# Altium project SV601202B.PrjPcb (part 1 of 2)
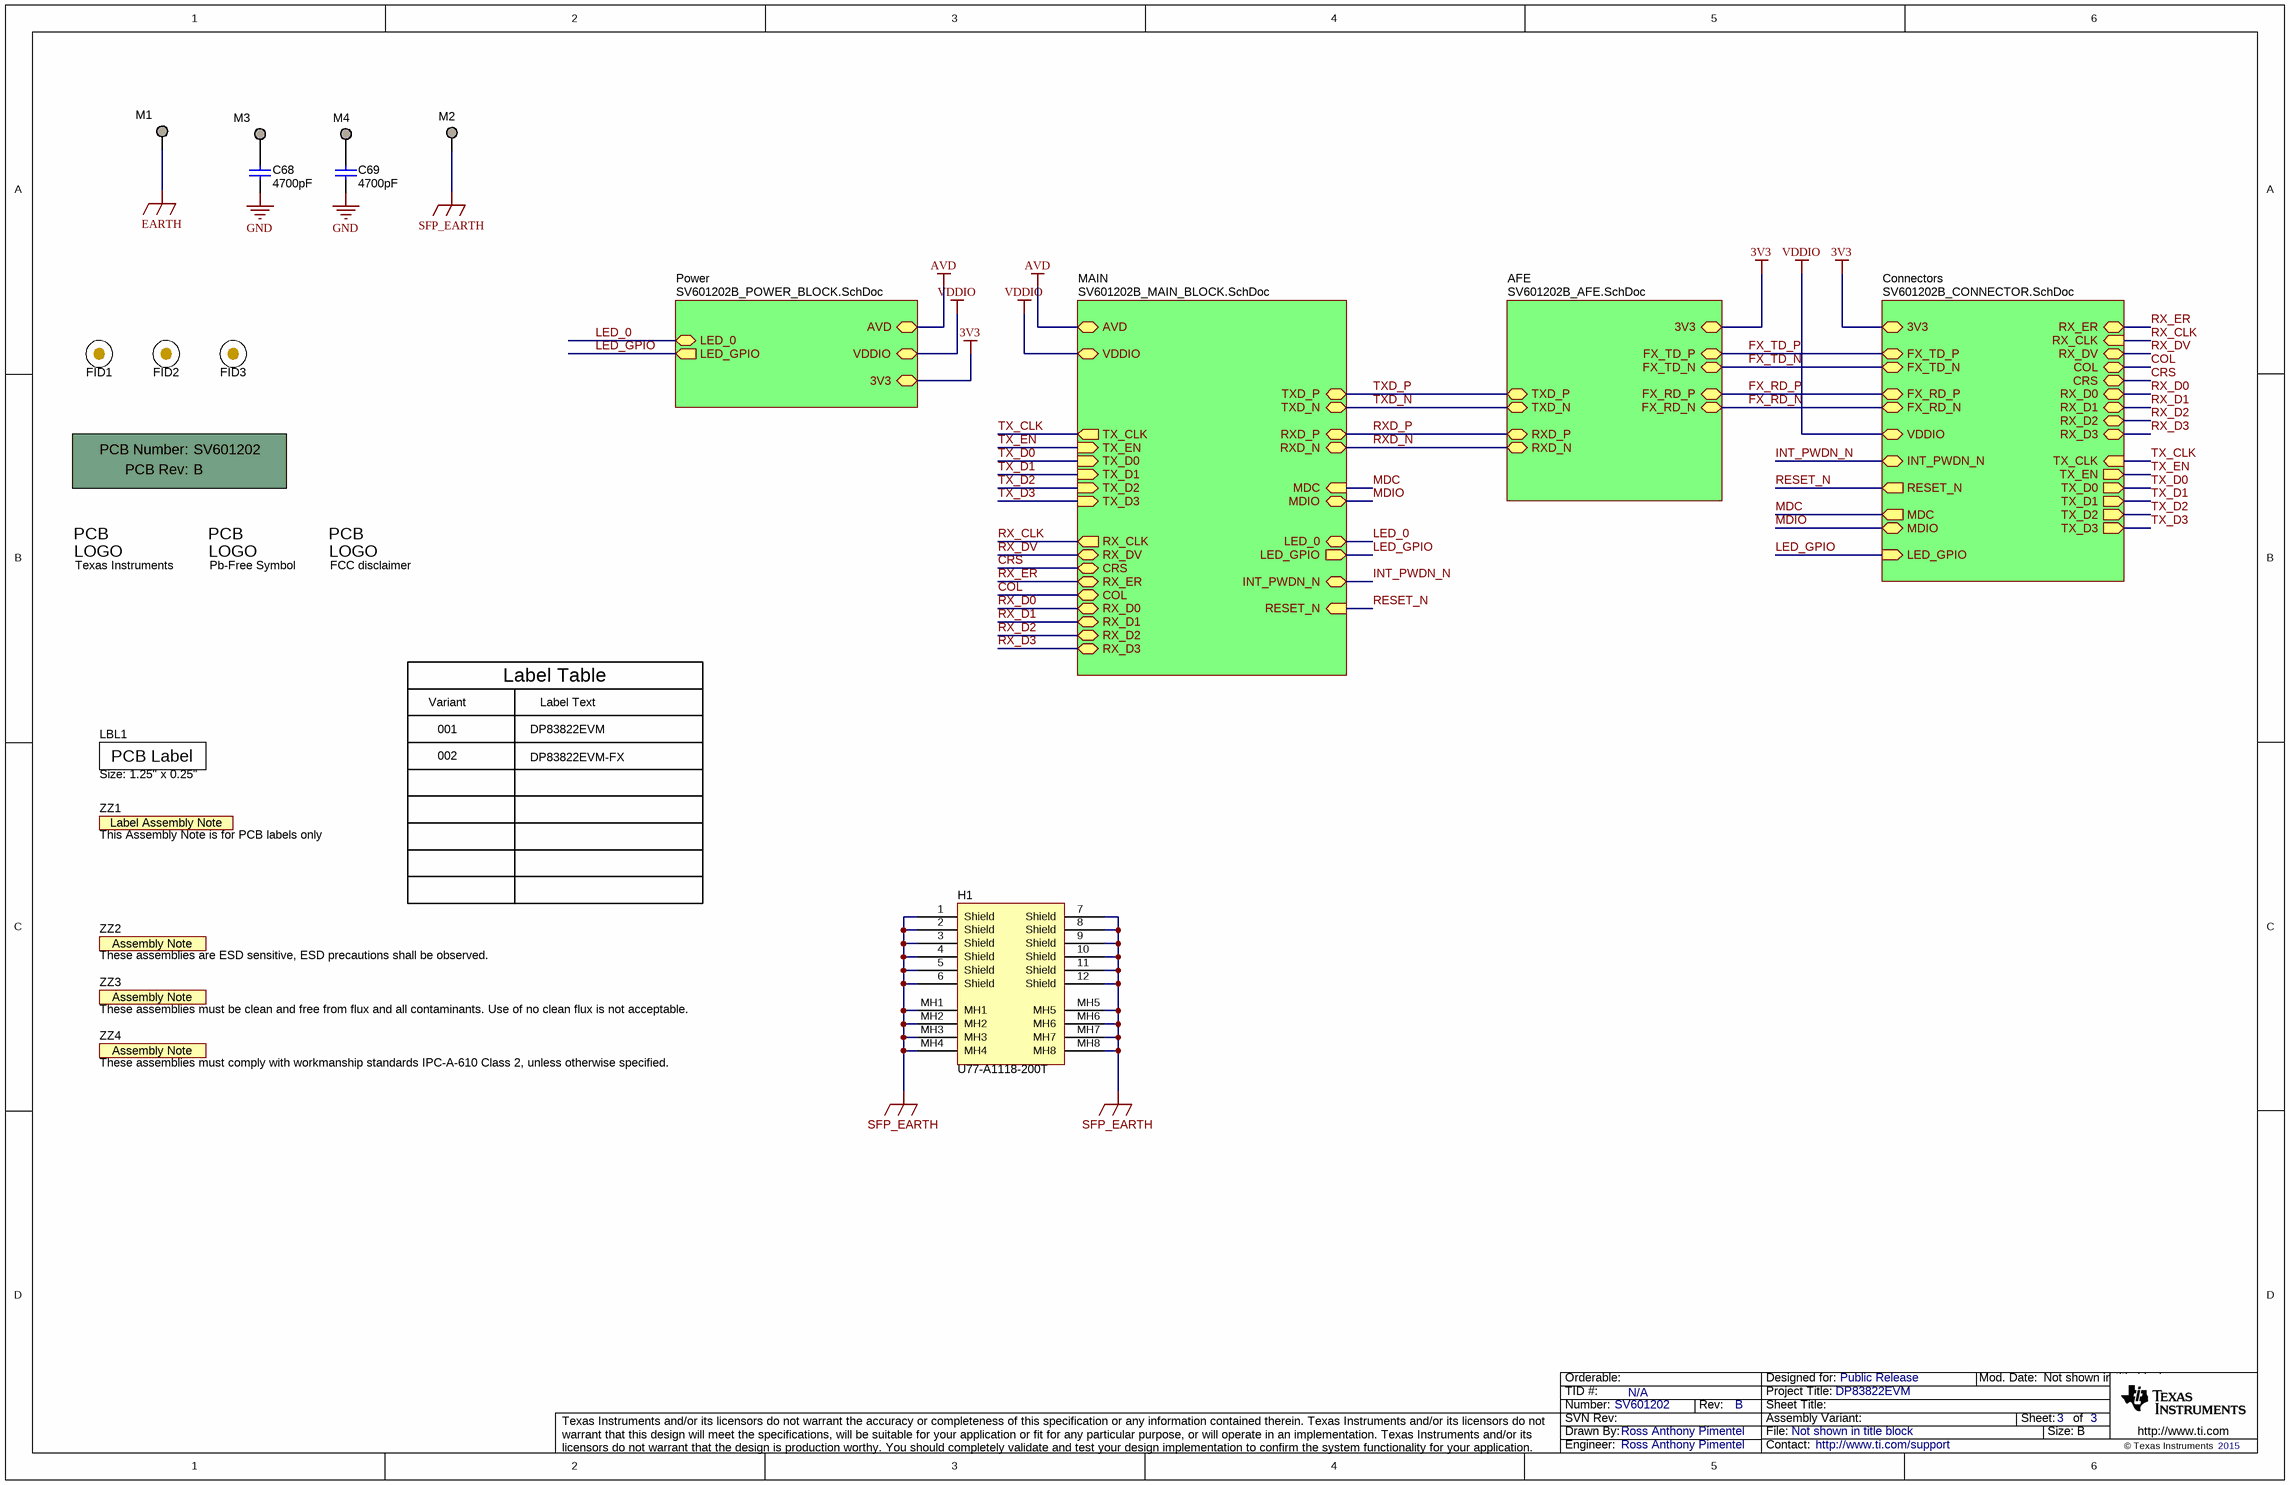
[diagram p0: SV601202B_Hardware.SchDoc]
CopyrightYear: 2015; PCB_Layout: Matthew Dillingham; PCB_Rev: B; PRJ_Customer: Public Release; PRJ_Engineer: Ross Anthony Pimentel; PRJ_Number: SV601202; PRJ_Title: DP83822EVM; SCH_Rev: B; TechSupport: http://www.ti.com/support; TID: N/A
5 sheets, 231 parts. Net scope: hierarchical (ports join the sheet entries above them; power ports are global).
Board file: SV601202B.PcbDoc
Sheets:
  SV601202B_Hardware.SchDoc
    AFE = SV601202B_AFE.SchDoc
    MAIN = SV601202B_MAIN_BLOCK.SchDoc
    Power = SV601202B_POWER_BLOCK.SchDoc
    Connectors = SV601202B_CONNECTOR.SchDoc

## Sheet SV601202B_Hardware.SchDoc
size 431 x 279 mm; Date: Not shown in title block; ApprovedBy: Not shown in title block; CheckedBy: Not shown in title block; Author: Not shown in title block; CompanyName: Not shown in title block; DrawnBy: Ross Anthony Pimentel; Engineer: Not shown in title block; Organization: Not shown in title block; Address1: Not shown in title block; Address2: Not shown in title block; Address3: Not shown in title block; Address4: Not shown in title block; DocumentNumber: 1; Revision: Use project parameter SCH_Rev; SheetNumber: 3; SheetTotal: 3; PageSetup: Record=PageOptions¦CenterHorizontal=True¦CenterVertical=True¦PrintScale=1.00¦XCorrection=1.00¦YCorrection=1.00¦PrintKind=0¦BorderSize=5000000¦LeftOffset=0¦BottomOffset=0¦Orientation=2¦PaperLength=1000¦PaperWidth=1000¦Scale=100¦PaperSource=15¦PrintQuality=600¦MediaType=1¦DitherType=10¦PaperKind=Letter¦PrintScaleMode=1

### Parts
!PCB1  Printed Circuit Board  (value not drawn)  (mechanical)
C68  ValueDisplayed: 4700pF  [0805_HV]  (hidden comment: 08051C472KAT2A)
C69  ValueDisplayed: 4700pF  [0805_HV]  (hidden comment: 08051C472KAT2A)
FID1  Fiducial  [Fiducial10-20]  (value not drawn)
FID2  Fiducial  [Fiducial10-20]  (value not drawn)
FID3  Fiducial  [Fiducial10-20]  (value not drawn)
H1  U77-A1118-200T  [Amphenol_U77-A1118-200T]
LBL1  Size: 1.25" x 0.25"  [Label_1250x250]
Logo1  Texas Instruments  [TI_Horizontal_Overlay_Medium]  (no BOM)
Logo2  Pb-Free Symbol  [Pb-Free_Overlay_Small]  (no BOM)
Logo3  FCC disclaimer  [FCC_disclaimer]  (no BOM)
M1  TESTPOINT  [TESTPOINT]  (value not drawn)  (no BOM)
M2  TESTPOINT  [TESTPOINT]  (value not drawn)  (no BOM)
M3  TESTPOINT  [TESTPOINT]  (value not drawn)  (no BOM)
M4  TESTPOINT  [TESTPOINT]  (value not drawn)  (no BOM)
ZZ1  This Assembly Note is for PCB labels only  [AssemblyNoteLabel]  (no BOM)
ZZ2  These assemblies are ESD sensitive, ESD precautions shall be observed.  [AssemblyNote]  (no BOM)
ZZ3  These assemblies must be clean and free from flux and all contaminants. Use of no clean flux is not acceptable.  [AssemblyNote]  (no BOM)
ZZ4  These assemblies must comply with workmanship standards IPC-A-610 Class 2, unless otherwise specified.  [AssemblyNote]  (no BOM)

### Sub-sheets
AFE = SV601202B_AFE.SchDoc: 3V3, RXD_P (bidir), RXD_N (bidir), TXD_P (bidir), TXD_N (bidir), FX_RD_P, FX_RD_N (bidir), FX_TD_P (bidir), FX_TD_N (bidir)
Connectors = SV601202B_CONNECTOR.SchDoc: 3V3, FX_TD_P (bidir), FX_TD_N (bidir), FX_RD_N (bidir), INT_PWDN_N (bidir), RESET_N (out), MDC (out), MDIO (bidir), LED_GPIO (in), TX_D3 (out), TX_D2 (out), TX_D1 (out), TX_D0 (out), TX_EN (out), TX_CLK (in), RX_D3 (bidir), RX_D2 (bidir), RX_D1 (bidir), RX_D0 (bidir), CRS (bidir), COL (bidir), RX_DV (bidir), RX_ER (bidir), RX_CLK (in), FX_RD_P, VDDIO
MAIN = SV601202B_MAIN_BLOCK.SchDoc: AVD, VDDIO, INT_PWDN_N (bidir), RESET_N (in), MDC (in), MDIO (bidir), TX_CLK (out), TX_EN (in), TX_D0 (in), TX_D1 (in), TX_D2 (in), TX_D3 (in), RX_CLK (out), RX_DV (bidir), RX_ER (bidir), CRS (bidir), COL (bidir), RX_D0 (bidir), RX_D1 (bidir), RX_D2 (bidir), RX_D3 (bidir), LED_GPIO (out), LED_0 (bidir), RXD_N (bidir), RXD_P (bidir), TXD_N (bidir), TXD_P (bidir)
Power = SV601202B_POWER_BLOCK.SchDoc: AVD, VDDIO, 3V3, LED_0 (bidir), LED_GPIO (out)

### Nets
3V3: sheet AFE/3V3, sheet Power/3V3, sheet Connectors/3V3
AVD: sheet MAIN/AVD, sheet Power/AVD
EARTH: M1.1
GND: C68.2 C69.2
SFP_EARTH: H1.1(Shield) H1.2(Shield) H1.3(Shield) H1.4(Shield) H1.5(Shield) H1.6(Shield) H1.7(Shield) H1.8(Shield) H1.9(Shield) H1.10(Shield) H1.11(Shield) H1.12(Shield) H1.MH1 H1.MH2 H1.MH3 H1.MH4 H1.MH5 H1.MH6 H1.MH7 H1.MH8 M2.1
VDDIO: sheet MAIN/VDDIO, sheet Power/VDDIO, sheet Connectors/VDDIO
COL: sheet MAIN/COL, sheet Connectors/COL
CRS: sheet MAIN/CRS, sheet Connectors/CRS
FX_RD_N: sheet AFE/FX_RD_N, sheet Connectors/FX_RD_N
FX_RD_P: sheet AFE/FX_RD_P, sheet Connectors/FX_RD_P
FX_TD_N: sheet AFE/FX_TD_N, sheet Connectors/FX_TD_N
FX_TD_P: sheet AFE/FX_TD_P, sheet Connectors/FX_TD_P
INT_PWDN_N: sheet MAIN/INT_PWDN_N, sheet Connectors/INT_PWDN_N
LED_0: sheet MAIN/LED_0, sheet Power/LED_0
LED_GPIO: sheet MAIN/LED_GPIO, sheet Power/LED_GPIO, sheet Connectors/LED_GPIO
MDC: sheet MAIN/MDC, sheet Connectors/MDC
MDIO: sheet MAIN/MDIO, sheet Connectors/MDIO
RESET_N: sheet MAIN/RESET_N, sheet Connectors/RESET_N
RX_CLK: sheet MAIN/RX_CLK, sheet Connectors/RX_CLK
RX_D0: sheet MAIN/RX_D0, sheet Connectors/RX_D0
RX_D1: sheet MAIN/RX_D1, sheet Connectors/RX_D1
RX_D2: sheet MAIN/RX_D2, sheet Connectors/RX_D2
RX_D3: sheet MAIN/RX_D3, sheet Connectors/RX_D3
RX_DV: sheet MAIN/RX_DV, sheet Connectors/RX_DV
RX_ER: sheet MAIN/RX_ER, sheet Connectors/RX_ER
RXD_N: sheet AFE/RXD_N, sheet MAIN/RXD_N
RXD_P: sheet AFE/RXD_P, sheet MAIN/RXD_P
TX_CLK: sheet MAIN/TX_CLK, sheet Connectors/TX_CLK
TX_D0: sheet MAIN/TX_D0, sheet Connectors/TX_D0
TX_D1: sheet MAIN/TX_D1, sheet Connectors/TX_D1
TX_D2: sheet MAIN/TX_D2, sheet Connectors/TX_D2
TX_D3: sheet MAIN/TX_D3, sheet Connectors/TX_D3
TX_EN: sheet MAIN/TX_EN, sheet Connectors/TX_EN
TXD_N: sheet AFE/TXD_N, sheet MAIN/TXD_N
TXD_P: sheet AFE/TXD_P, sheet MAIN/TXD_P
NetC68_1: C68.1 M3.1
NetC69_1: C69.1 M4.1

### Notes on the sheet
- Variant
- Label Table
- Label Text
- 001
- 002
- DP83822EVM
- DP83822EVM-FX

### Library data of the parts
!PCB1 = PCB: Manufacturer: Any; PartNumber: SV601202; SymbolCreator: a0412235
C68 C69 = 08051C472KAT2A: CAP, CERM, 4700 pF, 100 V, +/- 10%, X7R, 0805; Manufacturer: AVX; Polarized: N; CompType: Capacitor; Value: 4700pF; U/M: EA; Cap_F: 0.0000000047; Tolerance_%: 10; ESR_ohm: 0.119; Value1: 0.119 ohm; VDC_V: 100; Value2: 100V; TaMin_C: -55; TaMax_C: 125; Cap_Case: 0805
FID1-FID3 = Fiducial: Fiducial mark.  There is nothing to buy or mount.; SymbolCreator: codlsc
H1 = U77-A1118-200T: SFP Single Cage; Manufacturer: Amphenol Canada; SymbolCreator: Altium
LBL1 = THT-13-457-10: Thermal Transfer Printable Labels, 1.250" W x 0.250" H - 10,000 per roll; Manufacturer: Brady; SymbolCreator: a0412235; CompType: Label
Logo1 = TI_Logo: Texas Instrument Corporate Signature; SymbolCreator: a0412235
Logo2 = Pb-Free: SymbolCreator: a0412235
Logo3 = FCC_disclaimer: SymbolCreator: codlsc
M1-M4 = TESTPOINT: TEST POINT.  No entry in BOM.
ZZ1 = AssemblyNoteLabel: SymbolCreator: a0412235
ZZ2-ZZ4 = AssemblyNote: SymbolCreator: codlsc

## Sheet SV601202B_AFE.SchDoc
size 431 x 279 mm; Date: Not shown in title block; ApprovedBy: Not shown in title block; CheckedBy: Not shown in title block; Author: Not shown in title block; CompanyName: Not shown in title block; Engineer: Not shown in title block; Organization: Not shown in title block; Address1: Not shown in title block; Address2: Not shown in title block; Address3: Not shown in title block; Address4: Not shown in title block; DocumentNumber: 1; Revision: Use project parameter SCH_Rev; SheetNumber: 2; SheetTotal: 3; PageSetup: Record=PageOptions¦CenterHorizontal=True¦CenterVertical=True¦PrintScale=1.00¦XCorrection=1.00¦YCorrection=1.00¦PrintKind=0¦BorderSize=5000000¦LeftOffset=0¦BottomOffset=0¦Orientation=2¦PaperLength=1000¦PaperWidth=1000¦Scale=100¦PaperSource=15¦PrintQuality=600¦MediaType=1¦DitherType=10¦PaperKind=Letter¦PrintScaleMode=1
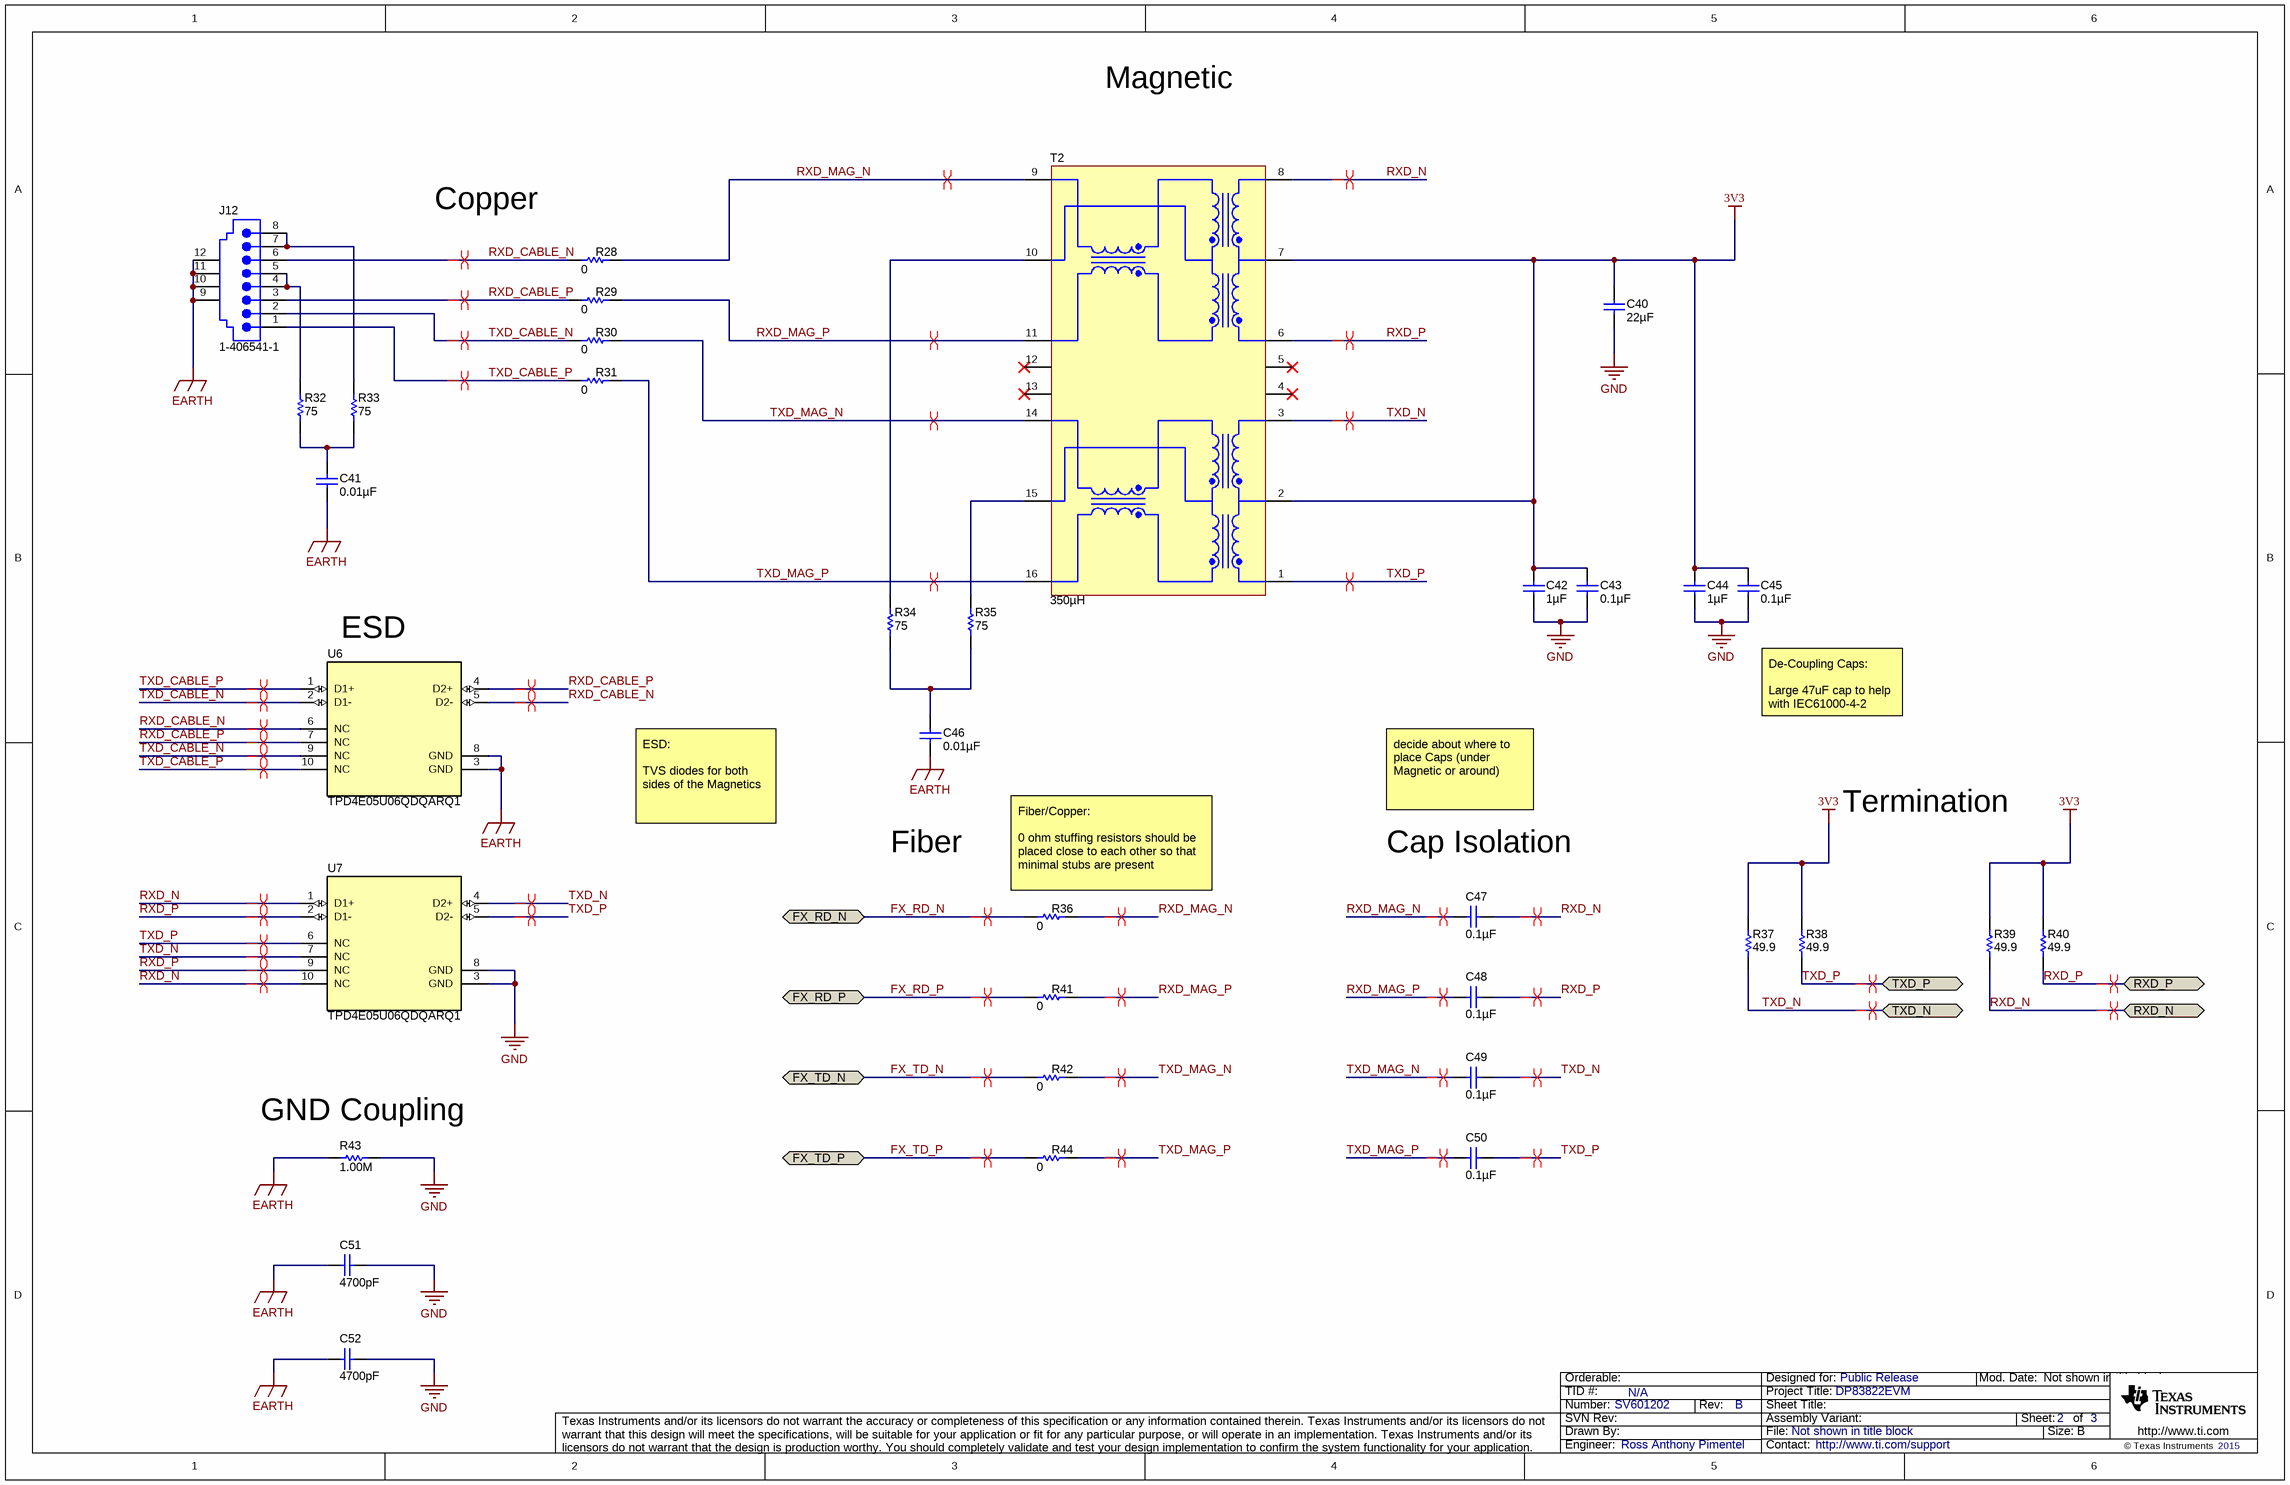
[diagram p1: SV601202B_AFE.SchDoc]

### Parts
C40  ValueDisplayed: 22µF  [1210_280]  (hidden comment: CGA6P1X7R1C226M250AC)
C41  ValueDisplayed: 0.01µF  [0805]  (hidden comment: CGA4J3C0G2E103J125AA)
C42  ValueDisplayed: 1µF  [0402]  (hidden comment: C1005X7S1A105K050BC)
C43  ValueDisplayed: 0.1µF  [0402]  (hidden comment: GRM155R71C104KA88D)
C44  ValueDisplayed: 1µF  [0402]  (hidden comment: C1005X7S1A105K050BC)
C45  ValueDisplayed: 0.1µF  [0402]  (hidden comment: GRM155R71C104KA88D)
C46  ValueDisplayed: 0.01µF  [0805_HV]  (hidden comment: CGA4J3C0G2E103J125AA)
C47  ValueDisplayed: 0.1µF  [0603]  (hidden comment: CGA3E2X8R1E104K080AA)
C48  ValueDisplayed: 0.1µF  [0603]  (hidden comment: CGA3E2X8R1E104K080AA)
C49  ValueDisplayed: 0.1µF  [0603]  (hidden comment: CGA3E2X8R1E104K080AA)
C50  ValueDisplayed: 0.1µF  [0603]  (hidden comment: CGA3E2X8R1E104K080AA)
C51  ValueDisplayed: 4700pF  [1812_254]  (hidden comment: 1812GC472KAT1A)
C52  ValueDisplayed: 4700pF  [1812_254]  (hidden comment: 1812GC472KAT1A)
J12  1-406541-1  [TEC_1-406541-1]
R28  ValueDisplayed: 0  [0201L]  (hidden comment: ERJ-1GE0R00C)
R29  ValueDisplayed: 0  [0201L]  (hidden comment: ERJ-1GE0R00C)
R30  ValueDisplayed: 0  [0201L]  (hidden comment: ERJ-1GE0R00C)
R31  ValueDisplayed: 0  [0201L]  (hidden comment: ERJ-1GE0R00C)
R32  ValueDisplayed: 75  [0805_HV]  (hidden comment: CRCW080575R0JNEA)
R33  ValueDisplayed: 75  [0805_HV]  (hidden comment: CRCW080575R0JNEA)
R34  ValueDisplayed: 75  [0805_HV]  (hidden comment: CRCW080575R0JNEA)
R35  ValueDisplayed: 75  [0805_HV]  (hidden comment: CRCW080575R0JNEA)
R36  ValueDisplayed: 0  [0201L]  (hidden comment: ERJ-1GE0R00C)
R37  ValueDisplayed: 49.9  [0402]  (hidden comment: CRCW040249R9FKED)
R38  ValueDisplayed: 49.9  [0402]  (hidden comment: CRCW040249R9FKED)
R39  ValueDisplayed: 49.9  [0402]  (hidden comment: CRCW040249R9FKED)
R40  ValueDisplayed: 49.9  [0402]  (hidden comment: CRCW040249R9FKED)
R41  ValueDisplayed: 0  [0201L]  (hidden comment: ERJ-1GE0R00C)
R42  ValueDisplayed: 0  [0201L]  (hidden comment: ERJ-1GE0R00C)
R43  ValueDisplayed: 1.00M  [1206]  (hidden comment: CRCW12061M00FKEA)
R44  ValueDisplayed: 0  [0201L]  (hidden comment: ERJ-1GE0R00C)
T2  ValueDisplayed: 350µH  [Pulse_HX1188FNLT]  (hidden comment: HX1188FNLT)
U6  TPD4E05U06QDQARQ1  [DQA0010A]
U7  TPD4E05U06QDQARQ1  [DQA0010A]

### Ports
FX_RD_N (bidir), FX_RD_P (bidir), FX_TD_N (bidir), FX_TD_P (bidir), RXD_N (bidir), RXD_P (bidir), TXD_N (bidir), TXD_P (bidir)

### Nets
3V3: C40.1 C42.1 C43.1 C44.1 C45.1 R37.2 R38.2 R39.2 R40.2 T2.2(TCT) T2.7(RCT)
EARTH: C41.2 C46.2 C51.2 C52.2 J12.9 J12.10 J12.11 J12.12 R43.1 U6.3(GND) U6.8(GND)
GND: C40.2 C42.2 C43.2 C44.2 C45.2 C51.1 C52.1 R43.2 U7.3(GND) U7.8(GND)
FX_RD_N: R36.2 ; port FX_RD_N
FX_RD_P: R41.2 ; port FX_RD_P
FX_TD_N: R42.2 ; port FX_TD_N
FX_TD_P: R44.2 ; port FX_TD_P
RXD_CABLE_N: J12.6 R28.2 U6.5(D2-) U6.6(NC)
RXD_CABLE_P: J12.3 R29.2 U6.4(D2+) U6.7(NC)
RXD_MAG_N: C47.1 R28.1 R36.1 T2.9(RX-)
RXD_MAG_P: C48.1 R29.1 R41.1 T2.11(RX+)
RXD_N: C47.2 R39.1 T2.8(RD-) U7.1(D1+) U7.10(NC) ; port RXD_N
RXD_P: C48.2 R40.1 T2.6(RD+) U7.2(D1-) U7.9(NC) ; port RXD_P
TXD_CABLE_N: J12.2 R30.2 U6.2(D1-) U6.9(NC)
TXD_CABLE_P: J12.1 R31.2 U6.1(D1+) U6.10(NC)
TXD_MAG_N: C49.1 R30.1 R42.1 T2.14(TX-)
TXD_MAG_P: C50.1 R31.1 R44.1 T2.16(TX+)
TXD_N: C49.2 R37.1 T2.3(TD-) U7.4(D2+) U7.7(NC) ; port TXD_N
TXD_P: C50.2 R38.1 T2.1(TD+) U7.5(D2-) U7.6(NC) ; port TXD_P
NetC41_1: C41.1 R32.1 R33.1
NetC46_1: C46.1 R34.1 R35.1
NetJ12_4: J12.4 J12.5 R32.2
NetJ12_7: J12.7 J12.8 R33.2
NetR34_2: R34.2 T2.10(CMT)
NetR35_2: R35.2 T2.15(CMT)

Not connected (* = marked no-connect by the designer): T2 4(NC)* 5(NC)* 12(NC)* 13(NC)*

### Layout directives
differential pair: FX_RD_N, FX_RD_P, FX_TD_N, FX_TD_P, RXD_CABLE_N, RXD_CABLE_P, RXD_MAG_N, RXD_MAG_P, RXD_N, RXD_P, TXD_CABLE_N, TXD_CABLE_P, TXD_MAG_N, TXD_MAG_P, TXD_N, TXD_P

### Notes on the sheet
- Magnetic
- Copper
- (near U6) ESD
- De-Coupling Caps:
  Large 47uF cap to help with IEC61000-4-2
- ESD:
  TVS diodes for both sides of the Magnetics
- decide about where to place Caps (under Magnetic or around)
- Termination
- Fiber
- (near R36) Fiber/Copper:
  0 ohm stuffing resistors should be placed close to each other so that minimal stubs are present
- Cap Isolation
- (near R43) GND Coupling

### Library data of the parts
C40 = CGA6P1X7R1C226M250AC: CAP, CERM, 22 µF, 16 V, +/- 20%, X7R, AEC-Q200 Grade 1, 1210; Manufacturer: TDK; Polarized: N; CompType: Capacitor; Value: 22uF; U/M: EA; Cap_F: 0.000022; Tolerance_%: 20; Value1: Unknown; VDC_V: 16; Value2: 16V; TaMin_C: -55; TaMax_C: 125; Cap_Case: 1210; AEC Category: Q200; AEC Qualified: Y; AEC Grade: 1
C41 = CGA4J3C0G2E103J125AA: CAP, CERM, 0.01 µF, 250 V, +/- 5%, C0G/NP0, AEC-Q200 Grade 1, 0805; Manufacturer: TDK; Polarized: N; CompType: Capacitor; Value: 0.01uF; U/M: EA; Cap_F: 0.00000001; Tolerance_%: 5; Value1: Unknown; VDC_V: 250; Value2: 250V; TaMin_C: -55; TaMax_C: 125; AEC Category: Q200; AEC Qualified: Y; AEC Grade: 1
C42 C44 = C1005X7S1A105K050BC: CAP, CERM, 1 µF, 10 V, +/- 10%, X7S, 0402; Manufacturer: TDK; Polarized: N; CompType: Capacitor; Value: 1uF; U/M: EA; Cap_F: 0.000001; Tolerance_%: 10; Value1: Unknown; Value2: 10V; TaMin_C: -55; TaMax_C: 125
C43 C45 = GRM155R71C104KA88D: CAP, CERM, 0.1 µF, 16 V, +/- 10%, X7R, 0402; Manufacturer: MuRata; Polarized: N; CompType: Capacitor; Value: 0.1uF; U/M: EA; Cap_F: 0.0000001; Tolerance_%: 10; Value1: Unknown; VDC_V: 16; Value2: 16V; TaMin_C: -55; TaMax_C: 125
C46 = CGA4J3C0G2E103J125AA: CAP, CERM, 0.01 µF, 250 V, +/- 5%, C0G/NP0, AEC-Q200 Grade 1, 0805; Manufacturer: TDK; Polarized: N; CompType: Capacitor; Value: 0.01uF; U/M: EA; Cap_F: 0.00000001; Tolerance_%: 5; Value1: Unknown; VDC_V: 250; Value2: 250V; TaMin_C: -55; TaMax_C: 125; Cap_Case: 0805; AEC Category: Q200; AEC Qualified: Y; AEC Grade: 1
C47-C50 = CGA3E2X8R1E104K080AA: CAP, CERM, 0.1 µF, 25 V, +/- 10%, X8R, AEC-Q200 Grade 0, 0603; Manufacturer: TDK; Polarized: N; CompType: Capacitor; Value: 0.1uF; U/M: EA; Cap_F: 0.0000001; Tolerance_%: 10; Value1: Unknown; VDC_V: 25; Value2: 25V; TaMin_C: -55; TaMax_C: 150; AEC Category: Q200; AEC Qualified: Y; AEC Grade: 0
C51 C52 = 1812GC472KAT1A: CAP, CERM, 4700 pF, 2000 V, +/- 10%, X7R, 1812; Manufacturer: AVX; Polarized: N; CompType: Capacitor; Value: 4700pF; U/M: EA; Cap_F: 0.0000000047; Tolerance_%: 10; Value1: Unknown; VDC_V: 2000; Value2: 2000V; TaMin_C: -55; TaMax_C: 125; Cap_Case: 1812
J12 = 1-406541-1: RJ-45, No LED, tab up, R/A, TH; Manufacturer: TE Connectivity; SymbolCreator: x0208326; CompType: Connector; ContactFinish: Gold
R28-R31 R36 R41 R42 R44 = ERJ-1GE0R00C: RES, 0, 5%, 0.05 W, 0201; Manufacturer: Panasonic; CompType: Resistor; Value: 0; Value_Code: 0000; Tolerance_%: 5; Power_W: 0.05; Value2: 0.05W; VDC_V: 15; TempCo: 600 ppm/C; EIA_Code: E24; U/M: EA; AEC Category: Q200
R32-R35 = CRCW080575R0JNEA: RES, 75, 5%, 0.125 W, 0805; Manufacturer: Vishay-Dale; CompType: Resistor; Value: 75; Value_Code: 75R0; Tolerance_%: 5; Power_W: 0.125; Value2: 0.125W; VDC_V: 150; TempCo: 200 ppm/C; EIA_Code: E24; U/M: EA; AEC Category: Q200
R37-R40 = CRCW040249R9FKED: RES, 49.9, 1%, 0.063 W, 0402; Manufacturer: Vishay-Dale; CompType: Resistor; Value: 49.9; Value_Code: 49R9; Tolerance_%: 1; Power_W: 0.063; Value2: 0.063W; VDC_V: 50; TempCo: 100 ppm/C; EIA_Code: E96; U/M: EA
R43 = CRCW12061M00FKEA: RES, 1.00 M, 1%, 0.25 W, 1206; Manufacturer: Vishay-Dale; CompType: Resistor; Value: 1.00Meg; Res_ohm: 1000000; Value_Code: 1M00; Tolerance_%: 1; Power_W: 0.25; Value2: 0.25W; VDC_V: 200; TempCo: 100 ppm/C; EIA_Code: E96; U/M: EA; AEC Category: Q200
T2 = HX1188FNLT: Transformer, 350 uH, SMT; Manufacturer: Pulse Engineering; SymbolCreator: Altium; Value: 350uH; Lp: 350
U6 U7 = TPD4E05U06QDQARQ1: 1, 4, 6 CHANNEL PROTECTION SOLUTION FOR SUPER-SPEED (UP TO 6 GBPS) INTERFACE, DQA0010A; Manufacturer: Texas Instruments; SymbolCreator: a0411947; CompType: IC; U/M: EA

## Sheet SV601202B_MAIN_BLOCK.SchDoc
size 431 x 279 mm; Date: Not shown in title block; ApprovedBy: Not shown in title block; CheckedBy: Not shown in title block; Author: Not shown in title block; CompanyName: Not shown in title block; Engineer: Not shown in title block; Organization: Not shown in title block; Address1: Not shown in title block; Address2: Not shown in title block; Address3: Not shown in title block; Address4: Not shown in title block; DocumentNumber: 1; Revision: Use project parameter SCH_Rev; SheetNumber: 2; SheetTotal: 3; PageSetup: Record=PageOptions¦CenterHorizontal=True¦CenterVertical=True¦PrintScale=1.00¦XCorrection=1.00¦YCorrection=1.00¦PrintKind=0¦BorderSize=5000000¦LeftOffset=0¦BottomOffset=0¦Orientation=2¦PaperLength=1000¦PaperWidth=1000¦Scale=100¦PaperSource=15¦PrintQuality=600¦MediaType=1¦DitherType=10¦PaperKind=Letter¦PrintScaleMode=1
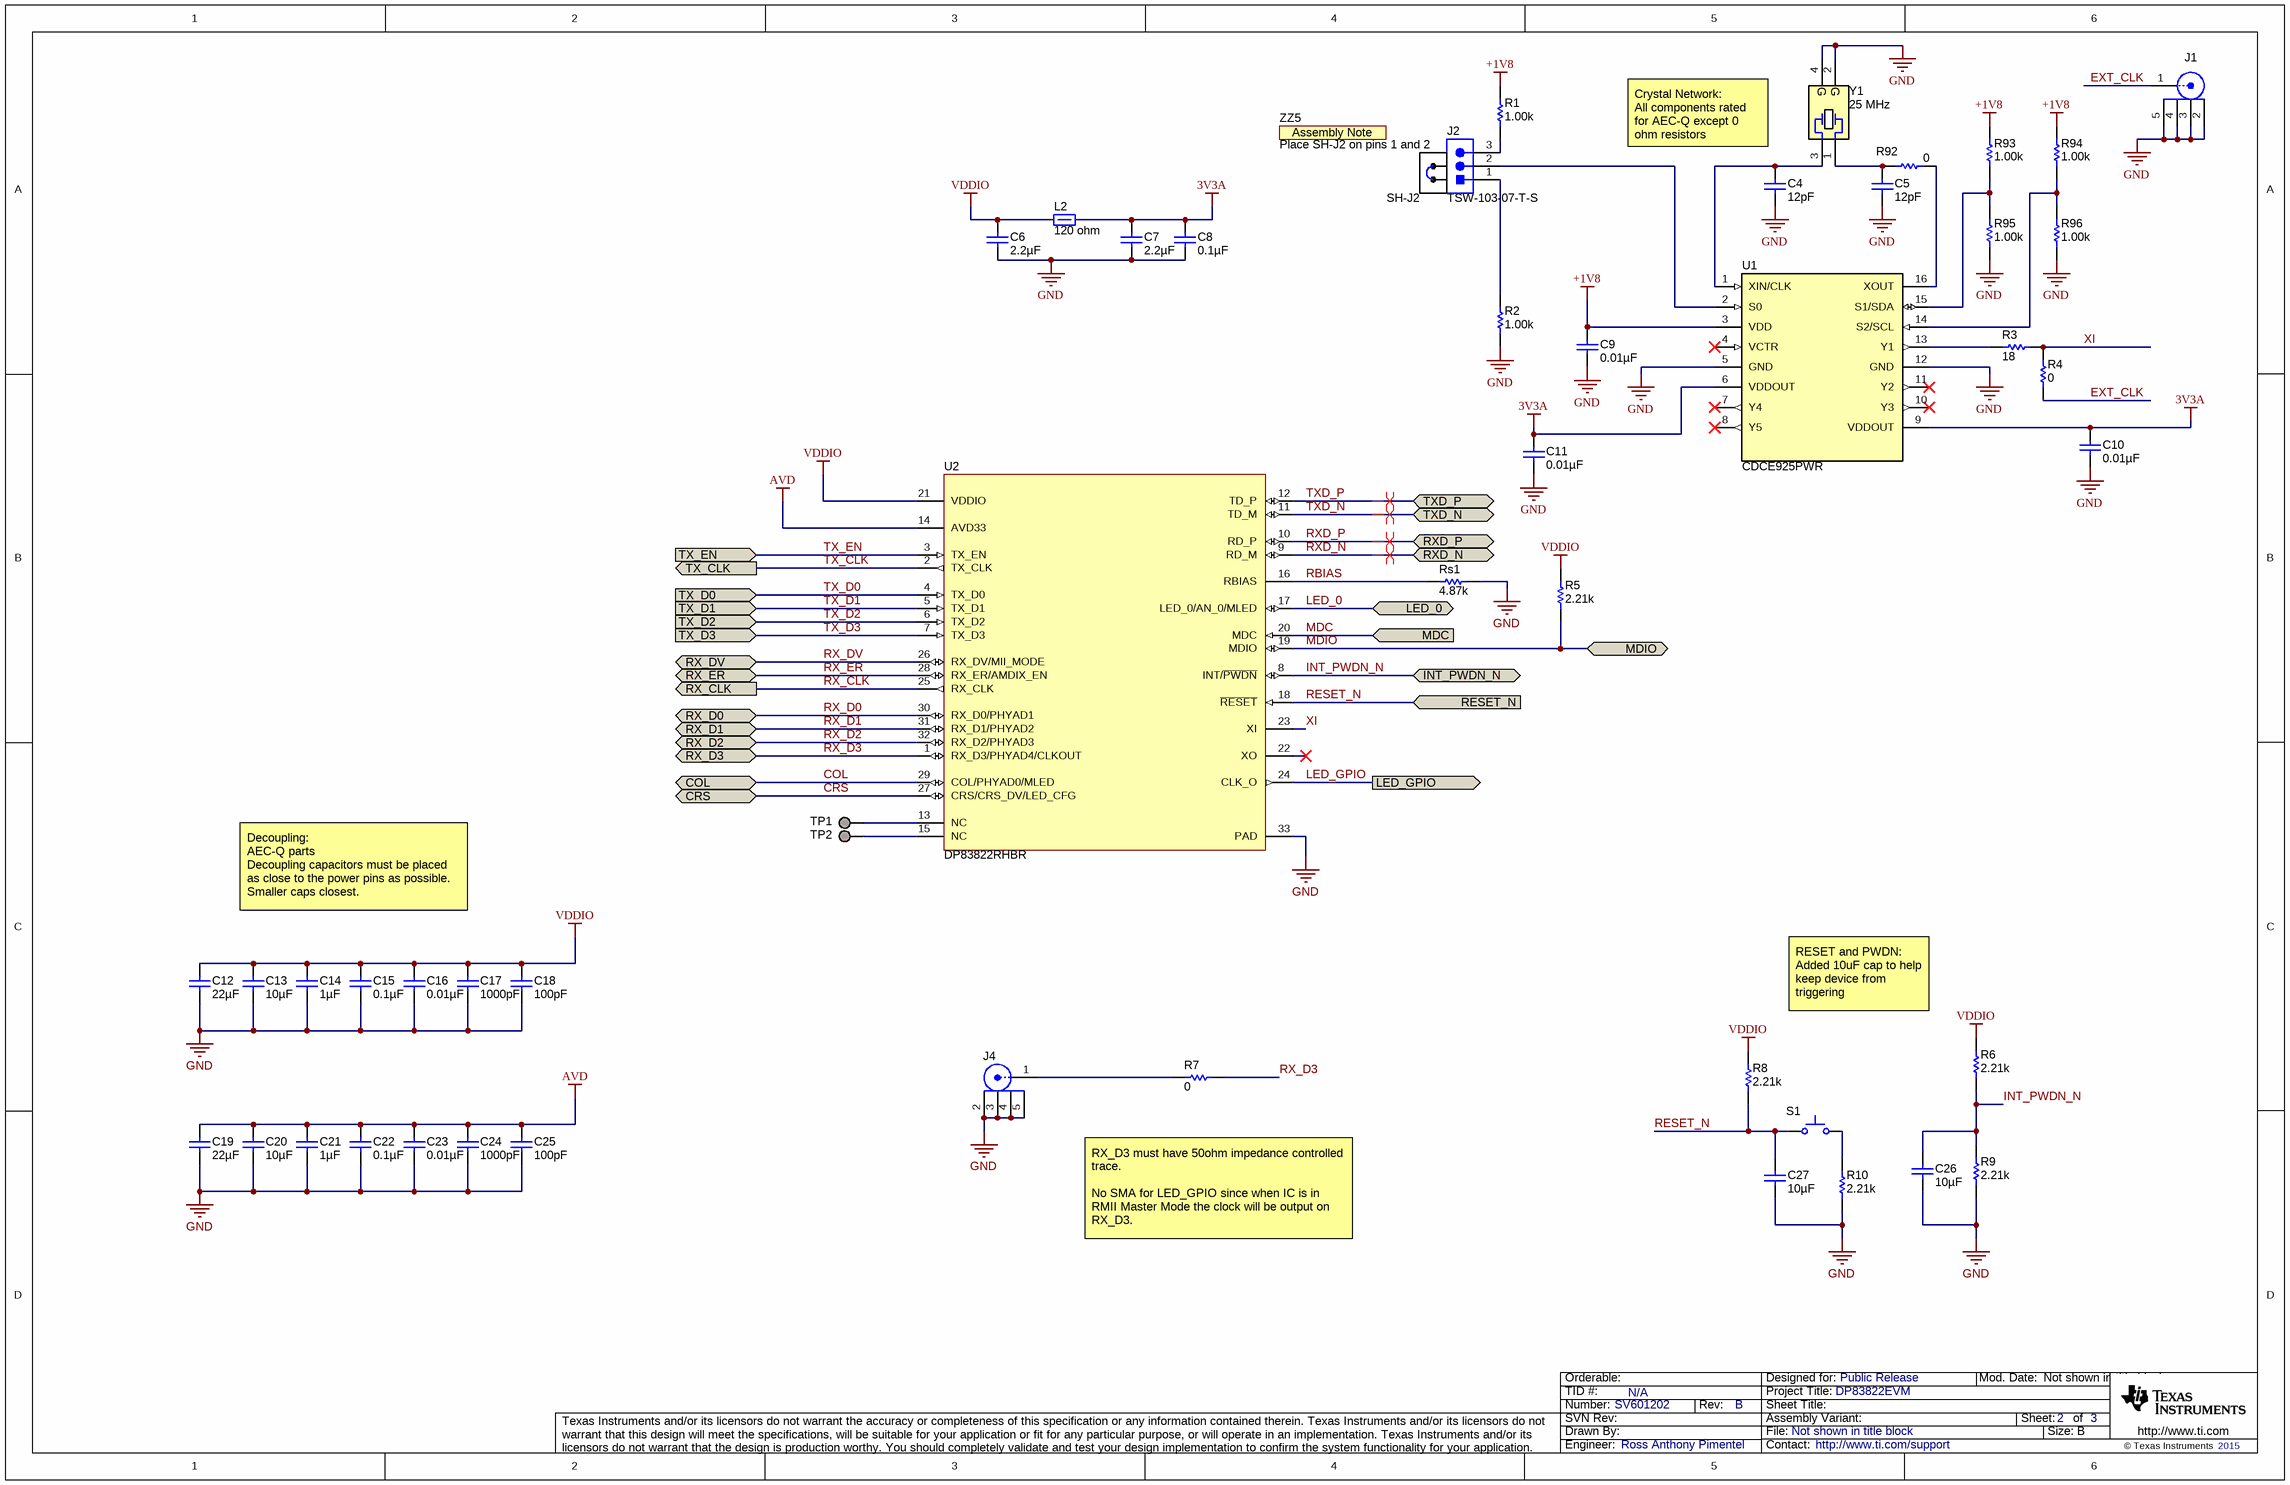
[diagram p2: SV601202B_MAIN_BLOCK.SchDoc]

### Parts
C4  ValueDisplayed: 12pF  [0402]  (hidden comment: C0402C120J3GACAUTO)
C5  ValueDisplayed: 12pF  [0402]  (hidden comment: C0402C120J3GACAUTO)
C6  ValueDisplayed: 2.2µF  [0402]  (hidden comment: GRM155R61C225KE11D)
C7  ValueDisplayed: 2.2µF  [0402]  (hidden comment: GRM155R61C225KE11D)
C8  ValueDisplayed: 0.1µF  [0402]  (hidden comment: GRM155R71C104KA88D)
C9  ValueDisplayed: 0.01µF  [0402]  (hidden comment: CGA2B3X7R1H103K050BB)
C10  ValueDisplayed: 0.01µF  [0402]  (hidden comment: CGA2B3X7R1H103K050BB)
C11  ValueDisplayed: 0.01µF  [0402]  (hidden comment: CGA2B3X7R1H103K050BB)
C12  ValueDisplayed: 22µF  [1210_280]  (hidden comment: CGA6P1X7R1C226M250AC)
C13  ValueDisplayed: 10µF  [1210_280]  (hidden comment: CGA6P1X7R1E106M250AC)
C14  ValueDisplayed: 1µF  [0402]  (hidden comment: C1005X7S1A105K050BC)
C15  ValueDisplayed: 0.1µF  [0402]  (hidden comment: GRM155R71C104KA88D)
C16  ValueDisplayed: 0.01µF  [0402]  (hidden comment: CGA2B3X7R1H103K050BB)
C17  ValueDisplayed: 1000pF  [0402]  (hidden comment: CGA2B2C0G1H102J050BA)
C18  ValueDisplayed: 100pF  [0402]  (hidden comment: CGA2B2C0G1H101J050BA)
C19  ValueDisplayed: 22µF  [1210_280]  (hidden comment: CGA6P1X7R1C226M250AC)
C20  ValueDisplayed: 10µF  [1210_280]  (hidden comment: CGA6P1X7R1E106M250AC)
C21  ValueDisplayed: 1µF  [0402]  (hidden comment: C1005X7S1A105K050BC)
C22  ValueDisplayed: 0.1µF  [0402]  (hidden comment: GRM155R71C104KA88D)
C23  ValueDisplayed: 0.01µF  [0402]  (hidden comment: CGA2B3X7R1H103K050BB)
C24  ValueDisplayed: 1000pF  [0402]  (hidden comment: CGA2B2C0G1H102J050BA)
C25  ValueDisplayed: 100pF  [0402]  (hidden comment: CGA2B2C0G1H101J050BA)
C26  ValueDisplayed: 10µF  [1210_280]  (hidden comment: CGA6P1X7R1E106M250AC)
C27  ValueDisplayed: 10µF  [1210_280]  (hidden comment: CGA6P1X7R1E106M250AC)
J1  External CLK  [Emerson_142-0701-851]  (value not drawn)
J2  TSW-103-07-T-S  [Samtec_TSW-103-07-T-S]
J4  RXD3  [Emerson_142-0701-851]  (value not drawn)
L2  value 120 ohm  [0805_HV]  (hidden comment: BLM21BD121SN1D)
R1  ValueDisplayed: 1.00k  [0402]  (hidden comment: CRCW04021K00FKED)
R2  ValueDisplayed: 1.00k  [0402]  (hidden comment: CRCW04021K00FKED)
R3  ValueDisplayed: 18  [0402]  (hidden comment: CRCW040218R0JNED)
R4  ValueDisplayed: 0  [0402]  (hidden comment: CRCW04020000Z0ED)
R5  ValueDisplayed: 2.21k  [TNPW0603]  (hidden comment: TNPW06032K21BEEA)
R6  ValueDisplayed: 2.21k  [TNPW0603]  (hidden comment: TNPW06032K21BEEA)
R7  ValueDisplayed: 0  [0201]  (hidden comment: ERJ-1GE0R00C)
R8  ValueDisplayed: 2.21k  [TNPW0603]  (hidden comment: TNPW06032K21BEEA)
R9  ValueDisplayed: 2.21k  [TNPW0603]  (hidden comment: TNPW06032K21BEEA)
R10  ValueDisplayed: 2.21k  [TNPW0603]  (hidden comment: TNPW06032K21BEEA)
R92  ValueDisplayed: 0  [0201M]  (hidden comment: ERJ-1GE0R00C)
R93  ValueDisplayed: 1.00k  [0201]  (hidden comment: CRCW02011K00FKED)
R94  ValueDisplayed: 1.00k  [0201]  (hidden comment: CRCW02011K00FKED)
R95  ValueDisplayed: 1.00k  [0201]  (hidden comment: CRCW02011K00FKED)
R96  ValueDisplayed: 1.00k  [0201]  (hidden comment: CRCW02011K00FKED)
Rs1  ValueDisplayed: 4.87k  [0402]  (hidden comment: CRCW04024K87FKED)
S1  KSR221GLFS  [KSR]  (value not drawn)
SH-J2  SPC02SYAN  [SPC02SYAN]  (value not drawn)
TP1  TESTPOINT  [TP_25MIL-SMT]  (value not drawn)  (no BOM)
TP2  TESTPOINT  [TP_25MIL-SMT]  (value not drawn)  (no BOM)
U1  CDCE925PWR  [PW0016A_N]
U2  DP83822RHBR  [RHB0032B]
Y1  Frequency: 25 MHz  [Abracon_ABM8AIG]  (hidden comment: ABM8AIG-25.000MHZ-12-2Z-T3)
ZZ5  Place SH-J2 on pins 1 and 2  [AssemblyNote]  (no BOM)

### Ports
COL (bidir), CRS (bidir), INT_PWDN_N (bidir), LED_0 (bidir), LED_GPIO (out), MDC (in), MDIO (bidir), RESET_N (in), RX_CLK (out), RX_D0 (bidir), RX_D1 (bidir), RX_D2 (bidir), RX_D3 (bidir), RX_DV (bidir), RX_ER (bidir), RXD_N (bidir), RXD_P (bidir), TX_CLK (out), TX_D0 (in), TX_D1 (in), TX_D2 (in), TX_D3 (in), TX_EN (in), TXD_N (bidir), TXD_P (bidir)

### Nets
3V3A: C7.1 C8.1 C10.1 C11.1 L2.2 U1.6(VDDOUT) U1.9(VDDOUT)
+1V8: C9.1 R1.2 R93.2 R94.2 U1.3(VDD)
AVD: C19.1 C20.1 C21.1 C22.1 C23.1 C24.1 C25.1 U2.14(AVD33)
GND: C4.2 C5.2 C6.2 C7.2 C8.2 C9.2 C10.2 C11.2 C12.2 C13.2 C14.2 C15.2 C16.2 C17.2 C18.2 C19.2 C20.2 C21.2 C22.2 C23.2 C24.2 C25.2 C26.2 C27.2 J1.2 J1.3 J1.4 J1.5 J4.2 J4.3 J4.4 J4.5 R2.1 R9.1 R10.1 R95.1 R96.1 Rs1.1 U1.5(GND) U1.12(GND) U2.33(PAD) Y1.2(GND) Y1.4(GND)
VDDIO: C6.1 C12.1 C13.1 C14.1 C15.1 C16.1 C17.1 C18.1 L2.1 R5.2 R6.2 R8.2 U2.21(VDDIO)
COL: U2.29(COL/PHYAD0/MLED) ; port COL
CRS: U2.27(CRS/CRS_DV/LED_CFG) ; port CRS
EXT_CLK: J1.1 R4.1
INT_PWDN_N: C26.1 R6.1 R9.2 U2.8(INT/~{PWDN}) ; port INT_PWDN_N
LED_0: U2.17(LED_0/AN_0/MLED) ; port LED_0
LED_GPIO: U2.24(CLK_O) ; port LED_GPIO
MDC: U2.20(MDC) ; port MDC
MDIO: R5.1 U2.19(MDIO) ; port MDIO
RBIAS: Rs1.2 U2.16(RBIAS)
RESET_N: C27.1 R8.1 S1.1 U2.18(~{RESET}) ; port RESET_N
RX_CLK: U2.25(RX_CLK) ; port RX_CLK
RX_D0: U2.30(RX_D0/PHYAD1) ; port RX_D0
RX_D1: U2.31(RX_D1/PHYAD2) ; port RX_D1
RX_D2: U2.32(RX_D2/PHYAD3) ; port RX_D2
RX_D3: R7.2 U2.1(RX_D3/PHYAD4/CLKOUT) ; port RX_D3
RX_DV: U2.26(RX_DV/MII_MODE) ; port RX_DV
RX_ER: U2.28(RX_ER/AMDIX_EN) ; port RX_ER
RXD_N: U2.9(RD_M) ; port RXD_N
RXD_P: U2.10(RD_P) ; port RXD_P
TX_CLK: U2.2(TX_CLK) ; port TX_CLK
TX_D0: U2.4(TX_D0) ; port TX_D0
TX_D1: U2.5(TX_D1) ; port TX_D1
TX_D2: U2.6(TX_D2) ; port TX_D2
TX_D3: U2.7(TX_D3) ; port TX_D3
TX_EN: U2.3(TX_EN) ; port TX_EN
TXD_N: U2.11(TD_M) ; port TXD_N
TXD_P: U2.12(TD_P) ; port TXD_P
XI: R3.2 R4.2 U2.23(XI)
NetC4_1: C4.1 U1.1(XIN/CLK) Y1.3
NetC5_1: C5.1 R92.1 Y1.1
NetJ2_1: J2.1 R2.2
NetJ2_2: J2.2 U1.2(S0)
NetJ2_3: J2.3 R1.1
NetJ4_1: J4.1 R7.1
NetR3_1: R3.1 U1.13(Y1)
NetR10_2: R10.2 S1.2
NetR92_2: R92.2 U1.16(XOUT)
NetR93_1: R93.1 R95.2 U1.15(S1/SDA)
NetR94_1: R94.1 R96.2 U1.14(S2/SCL)
NetTP1_1: TP1.1 U2.13(NC)
NetTP2_1: TP2.1 U2.15(NC)

Not connected (* = marked no-connect by the designer): U1 4(VCTR)* 7(Y4)* 8(Y5)* 10(Y3)* 11(Y2)*; U2 22(XO)*

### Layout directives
differential pair: RXD_N, RXD_P, TXD_N, TXD_P

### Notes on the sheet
- Crystal Network:
  All components rated for AEC-Q except 0 ohm resistors
- Decoupling:
  AEC-Q parts
  Decoupling capacitors must be placed as close to the power pins as possible. Smaller caps closest.
- RESET and PWDN:
  Added 10uF cap to help keep device from triggering
- RX_D3 must have 50ohm impedance controlled trace.
  No SMA for LED_GPIO since when IC is in RMII Master Mode the clock will be output on RX_D3.

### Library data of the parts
C4 C5 = C0402C120J3GACAUTO: CAP, CERM, 12 pF, 25 V, +/- 5%, C0G/NP0, AEC-Q200 Grade 1, 0402; Manufacturer: Kemet; Polarized: N; CompType: Capacitor; Value: 12pF; U/M: EA; Cap_F: 0.000000000012; Tolerance_%: 5; Value1: Unknown; VDC_V: 25; Value2: 25V; TaMin_C: -55; TaMax_C: 125; AEC Category: Q200; AEC Qualified: Y; AEC Grade: 1
C6 C7 = GRM155R61C225KE11D: CAP, CERM, 2.2 µF, 16 V, +/- 10%, X5R, 0402; Manufacturer: MuRata; Polarized: N; CompType: Capacitor; Value: 2.2uF; U/M: EA; Cap_F: 0.0000022; Tolerance_%: 10; Value1: Unknown; VDC_V: 16; Value2: 16V; TaMin_C: -55; TaMax_C: 85; AEC Category: Q200
C8 C15 C22 = GRM155R71C104KA88D: as C43 on sheet SV601202B_AFE
C9-C11 C16 C23 = CGA2B3X7R1H103K050BB: CAP, CERM, 0.01 µF, 50 V, +/- 10%, X7R, AEC-Q200 Grade 1, 0402; Manufacturer: TDK; Polarized: N; CompType: Capacitor; Value: 0.01uF; U/M: EA; Cap_F: 0.00000001; Tolerance_%: 10; Value1: Unknown; VDC_V: 50; Value2: 50V; TaMin_C: -55; TaMax_C: 125; AEC Category: Q200; AEC Qualified: Y; AEC Grade: 1
C12 C19 = CGA6P1X7R1C226M250AC: as C40 on sheet SV601202B_AFE
C13 C20 C26 C27 = CGA6P1X7R1E106M250AC: CAP, CERM, 10 µF, 25 V, +/- 20%, X7R, AEC-Q200 Grade 1, 1210; Manufacturer: TDK; Polarized: N; CompType: Capacitor; Value: 10uF; U/M: EA; Cap_F: 0.00001; Tolerance_%: 20; Value1: Unknown; VDC_V: 25; Value2: 25V; TaMin_C: -55; TaMax_C: 125; Cap_Case: 1210; AEC Category: Q200; AEC Qualified: Y; AEC Grade: 1
C14 C21 = C1005X7S1A105K050BC: as C42 on sheet SV601202B_AFE
C17 C24 = CGA2B2C0G1H102J050BA: CAP, CERM, 1000 pF, 50 V, +/- 5%, C0G/NP0, AEC-Q200 Grade 1, 0402; Manufacturer: TDK; Polarized: N; CompType: Capacitor; Value: 1000pF; U/M: EA; Cap_F: 0.000000001; Tolerance_%: 5; Value1: Unknown; VDC_V: 50; Value2: 50V; TaMin_C: -55; TaMax_C: 125; AEC Category: Q200; AEC Qualified: Y; AEC Grade: 1
C18 C25 = CGA2B2C0G1H101J050BA: CAP, CERM, 100 pF, 50 V, +/- 5%, C0G/NP0, AEC-Q200 Grade 1, 0402; Manufacturer: TDK; Polarized: N; CompType: Capacitor; Value: 100pF; U/M: EA; Cap_F: 0.0000000001; Tolerance_%: 5; Value1: Unknown; VDC_V: 50; Value2: 50V; TaMin_C: -55; TaMax_C: 125; AEC Category: Q200; AEC Qualified: Y; AEC Grade: 1
J1 J4 = 142-0701-851: Connector, End launch SMA, 50 ohm, SMT; Manufacturer: Emerson Network Power; SymbolCreator: X0208326; U/M: EA
J2 = TSW-103-07-T-S: Header, 2.54 mm, 3x1, Tin, TH; Manufacturer: Samtec; SymbolCreator: a0799628; Pitch_mm: 2.54; Gender: Male; Shrouded: N; Row_Count: 1; Current_A: 6.3; Voltage_V: 550; Cert_CSA: Y
L2 = BLM21BD121SN1D: Ferrite Bead, 120 ohm @ 100 MHz, 0.2 A, 0805; Manufacturer: MuRata; Imax_A: 0.2; DCR_ohm: 0.25; Value1: 0.25 ohm; Value2: 0.2A; ZTyp@100MHz_Ohm: 120
R1 R2 = CRCW04021K00FKED: RES, 1.00 k, 1%, 0.063 W, 0402; Manufacturer: Vishay-Dale; CompType: Resistor; Value: 1.00k; Res_ohm: 1000; Value_Code: 1k00; Tolerance_%: 1; Power_W: 0.063; Value2: 0.063W; VDC_V: 50; TempCo: 100 ppm/C; EIA_Code: E96; U/M: EA; AEC Category: Q200
R3 = CRCW040218R0JNED: RES, 18, 5%, 0.063 W, 0402; Manufacturer: Vishay-Dale; CompType: Resistor; Value: 18; Value_Code: 18R0; Tolerance_%: 5; Power_W: 0.063; Value2: 0.063W; VDC_V: 50; TempCo: 200 ppm/C; EIA_Code: E24; U/M: EA; AEC Category: Q200
R4 = CRCW04020000Z0ED: RES, 0, 5%, 0.063 W, 0402; Manufacturer: Vishay-Dale; CompType: Resistor; Value: 0; Value_Code: 0000; Tolerance_%: 5; Power_W: 0.063; Value2: 0.063W; VDC_V: 50; TempCo: 200 ppm/C; EIA_Code: E24; U/M: EA; AEC Category: Q200
R5 R6 R8-R10 = TNPW06032K21BEEA: RES, 2.21 k, 0.1%, 0.1 W, AEC-Q200 Grade 0, 0603; Manufacturer: Vishay-Dale; CompType: Resistor; Value: 2.21k; Res_ohm: 2210; Value_Code: 2k21; Tolerance_%: 0.1; Value2: 0.1W; VDC_V: 75; TempCo: 25 ppm/C; EIA_Code: E192; U/M: EA; AEC Category: Q200; AEC Qualified: Y; AEC Grade: 0
R7 R92 = ERJ-1GE0R00C: as R28 on sheet SV601202B_AFE
R93-R96 = CRCW02011K00FKED: RES, 1.00 k, 1%, 0.05 W, 0201; Manufacturer: Vishay-Dale; CompType: Resistor; Value: 1.00k; Res_ohm: 1000; Value_Code: 1k00; Tolerance_%: 1; Power_W: 0.05; Value2: 0.05W; VDC_V: 30; TempCo: 100 ppm/C; EIA_Code: E96; U/M: EA; AEC Category: Q200
Rs1 = CRCW04024K87FKED: RES, 4.87 k, 1%, 0.063 W, 0402; Manufacturer: Vishay-Dale; CompType: Resistor; Value: 4.87k; Res_ohm: 4870; Value_Code: 4k87; Tolerance_%: 1; Power_W: 0.063; Value2: 0.063W; VDC_V: 50; TempCo: 100 ppm/C; EIA_Code: E96; U/M: EA; AEC Category: Q200
S1 = KSR221GLFS: Switch, Normally open, 2.3N force, 200k operations, SMD; Manufacturer: C&K Components; Circuit: SPST Switch; VDC_V: 32; SwitchFunction: Off-Mom; PositionCount: 1; CurrentRating_mA: 1001
SH-J2 = SPC02SYAN: Shunt, 100mil, Flash Gold, Black; Manufacturer: Sullins Connector Solutions; Value: 1x2; Note: You can "mate" this to a header by matching the designator.  i.e. use SH-J3 for header J3
TP1 TP2 = TESTPOINT: TEST POINT.  No entry in BOM.
U1 = CDCE925PWR: PROGRAMMABLE 2-PLL VCXO CLOCK SYNTHESIZER WITH 1.8-V, 2.5-V and 3.3-V LVCMOS OUTPUTS, PW0016A; Manufacturer: Texas Instruments; SymbolCreator: Altium; CompType: IC; U/M: EA
U2 = DP83822RHBR: 10/100 Ethernet PHY, RHB0032B; Alternate PartNumber: DP83822RHBT; Manufacturer: Texas Instruments; SymbolCreator: Altium; CompType: IC; U/M: EA
Y1 = ABM8AIG-25.000MHZ-12-2Z-T3: Crystal, 25MHz, 12pF, SMD; Manufacturer: Abracon Corporation; SymbolCreator: a0412235; U/M: EA; TaMin_C: -40; TaMax_C: 125; Frequency Stability: ±50ppm; SizeAreaWB_mm2: 14.7; SizeArea_mm2: 8; SizeX_mm: 2.5; SizeY_mm: 3.2; SizeZ_mm: 0.8
ZZ5 = Assembly Note: SymbolCreator: codlsc

## Sheet SV601202B_POWER_BLOCK.SchDoc
size 431 x 279 mm; Date: Not shown in title block; ApprovedBy: Not shown in title block; CheckedBy: Not shown in title block; Author: Not shown in title block; CompanyName: Not shown in title block; Engineer: Not shown in title block; Organization: Not shown in title block; Address1: Not shown in title block; Address2: Not shown in title block; Address3: Not shown in title block; Address4: Not shown in title block; DocumentNumber: 1; Revision: Use project parameter SCH_Rev; SheetNumber: 2; SheetTotal: 3; PageSetup: Record=PageOptions¦CenterHorizontal=True¦CenterVertical=True¦PrintScale=1.00¦XCorrection=1.00¦YCorrection=1.00¦PrintKind=0¦BorderSize=5000000¦LeftOffset=0¦BottomOffset=0¦Orientation=2¦PaperLength=1000¦PaperWidth=1000¦Scale=100¦PaperSource=15¦PrintQuality=600¦MediaType=1¦DitherType=10¦PrintScaleMode=1¦PaperKind=Letter
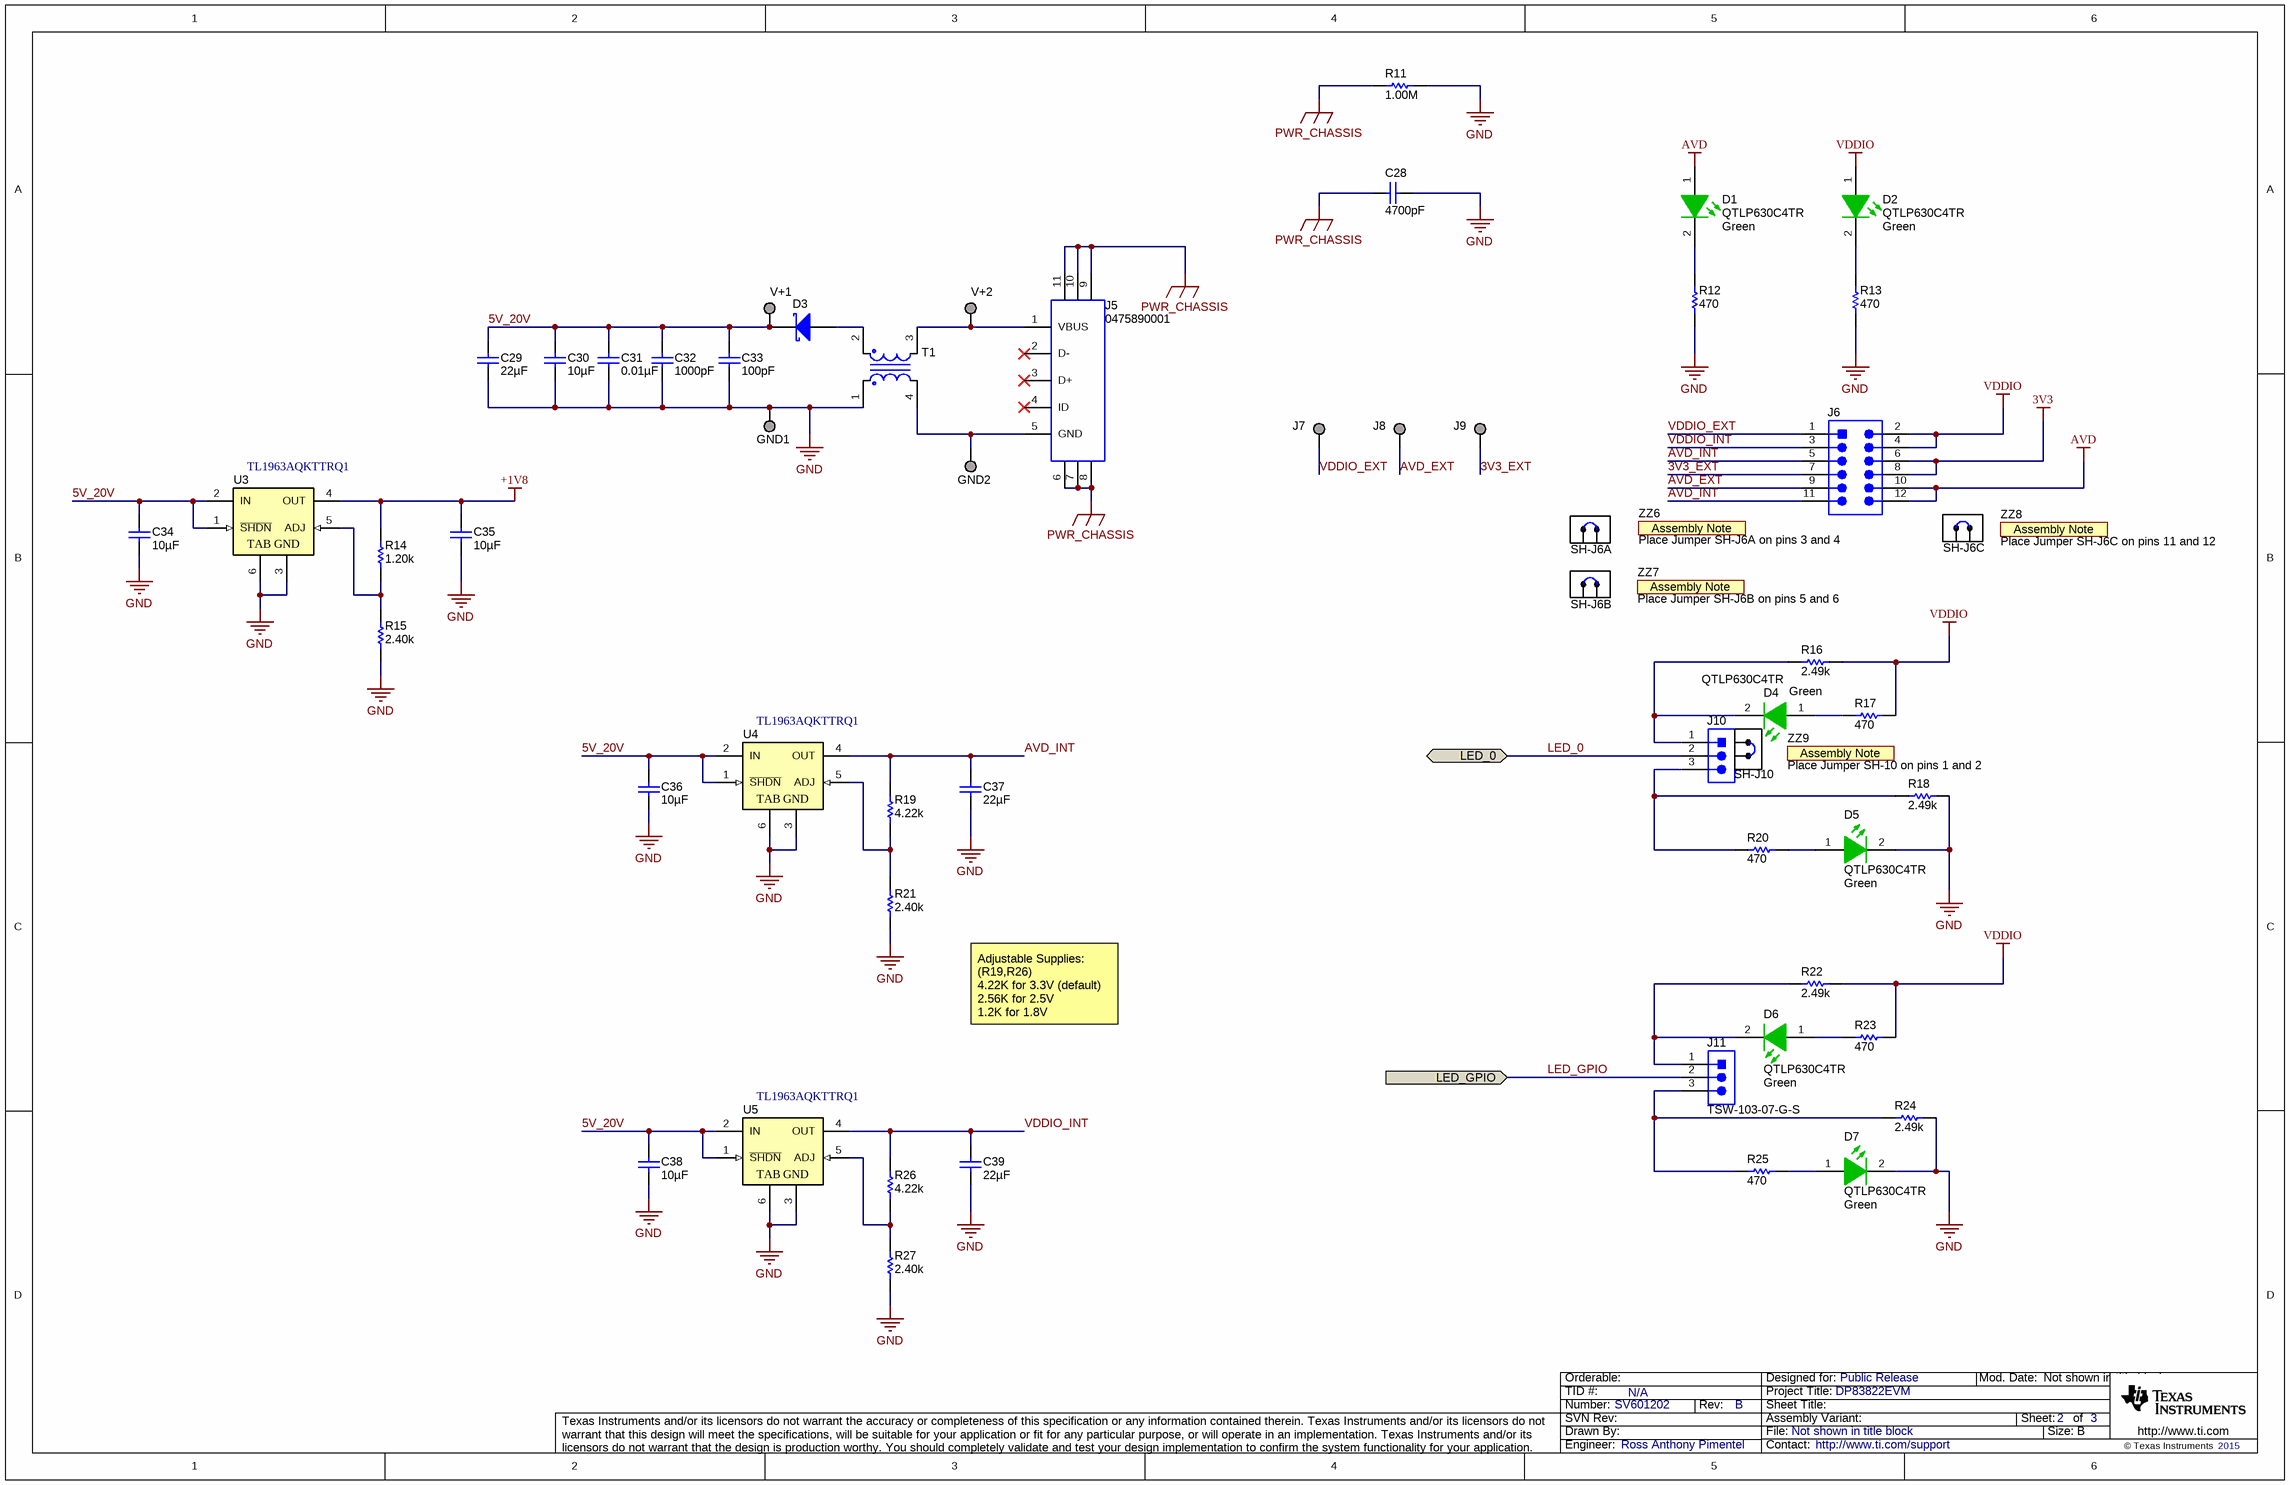
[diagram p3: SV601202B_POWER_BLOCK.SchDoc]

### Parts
C28  ValueDisplayed: 4700pF  [1812_254]  (hidden comment: 1812GC472KAT1A)
C29  ValueDisplayed: 22µF  [1210_280]  (hidden comment: CGA6P1X7R1C226M250AC)
C30  ValueDisplayed: 10µF  [1210_280]  (hidden comment: CGA6P1X7R1E106M250AC)
C31  ValueDisplayed: 0.01µF  [0402]  (hidden comment: CGA2B3X7R1H103K050BB)
C32  ValueDisplayed: 1000pF  [0402]  (hidden comment: CGA2B2C0G1H102J050BA)
C33  ValueDisplayed: 100pF  [0402]  (hidden comment: CGA2B2C0G1H101J050BA)
C34  ValueDisplayed: 10µF  [1210_280]  (hidden comment: CGA6P1X7R1E106M250AC)
C35  ValueDisplayed: 10µF  [1210_280]  (hidden comment: CGA6P1X7R1E106M250AC)
C36  ValueDisplayed: 10µF  [1210_280]  (hidden comment: CGA6P1X7R1E106M250AC)
C37  ValueDisplayed: 22µF  [1210_280]  (hidden comment: CGA6P1X7R1C226M250AC)
C38  ValueDisplayed: 10µF  [1210_280]  (hidden comment: CGA6P1X7R1E106M250AC)
C39  ValueDisplayed: 22µF  [1210_280]  (hidden comment: CGA6P1X7R1C226M250AC)
D1  QTLP630C4TR  value Green  [QTLP630C_Green]
D2  QTLP630C4TR  value Green  [QTLP630C_Green]
D3  NRVBA160T3G  [SMA]  (value not drawn)
D4  QTLP630C4TR  value Green  [QTLP630C_Green]
D5  QTLP630C4TR  value Green  [QTLP630C_Green]
D6  QTLP630C4TR  value Green  [QTLP630C_Green]
D7  QTLP630C4TR  value Green  [QTLP630C_Green]
GND1  Suggest using a net name here  [Keystone1502-2]  (value not drawn)
GND2  Suggest using a net name here  [Keystone1502-2]  (value not drawn)
J5  0475890001  [Molex_0475890001]
J6  TSW-106-07-G-D  [TSW-106-07-G-D]  (value not drawn)
J7  External VDDIO  [Keystone1502-2]  (value not drawn)
J8  External AVD  [Keystone1502-2]  (value not drawn)
J9  External CT  [Keystone1502-2]  (value not drawn)
J10  TSW-103-07-G-S  [TSW-103-07-G-S]  (value not drawn)
J11  TSW-103-07-G-S  [TSW-103-07-G-S]
R11  ValueDisplayed: 1.00M  [1206]  (hidden comment: CRCW12061M00FKEA)
R12  ValueDisplayed: 470  [0402]  (hidden comment: CRCW0402470RJNED)
R13  ValueDisplayed: 470  [0402]  (hidden comment: CRCW0402470RJNED)
R14  ValueDisplayed: 1.20k  [0603]  (hidden comment: RT0603BRD071K2L)
R15  ValueDisplayed: 2.40k  [0603]  (hidden comment: ERA-3AEB242V)
R16  ValueDisplayed: 2.49k  [0402]  (hidden comment: CRCW04022K49FKED)
R17  ValueDisplayed: 470  [0402]  (hidden comment: CRCW0402470RJNED)
R18  ValueDisplayed: 2.49k  [0402]  (hidden comment: CRCW04022K49FKED)
R19  ValueDisplayed: 4.22k  [0603]  (hidden comment: CRCW06034K22FKEA)
R20  ValueDisplayed: 470  [0402]  (hidden comment: CRCW0402470RJNED)
R21  ValueDisplayed: 2.40k  [0603]  (hidden comment: ERA-3AEB242V)
R22  ValueDisplayed: 2.49k  [0402]  (hidden comment: CRCW04022K49FKED)
R23  ValueDisplayed: 470  [0402]  (hidden comment: CRCW0402470RJNED)
R24  ValueDisplayed: 2.49k  [0402]  (hidden comment: CRCW04022K49FKED)
R25  ValueDisplayed: 470  [0402]  (hidden comment: CRCW0402470RJNED)
R26  ValueDisplayed: 4.22k  [0603]  (hidden comment: CRCW06034K22FKEA)
R27  ValueDisplayed: 2.40k  [0603]  (hidden comment: ERA-3AEB242V)
SH-J6A  SPC02SYAN  [SPC02SYAN]  (value not drawn)
SH-J6B  SPC02SYAN  [SPC02SYAN]  (value not drawn)
SH-J6C  SPC02SYAN  [SPC02SYAN]  (value not drawn)
SH-J10  SPC02SYAN  [SPC02SYAN]  (value not drawn)
T1  ACM9070-701-2PL  [ACM9070]  (value not drawn)
U3  TL1963AQKTTRQ1  [KTT0005A_N]
U4  TL1963AQKTTRQ1  [KTT0005A_N]
U5  TL1963AQKTTRQ1  [KTT0005A_N]
V+1  Suggest using a net name here  [Keystone1502-2]  (value not drawn)
V+2  Suggest using a net name here  [Keystone1502-2]  (value not drawn)
ZZ6  Place Jumper SH-J6A on pins 3 and 4  [AssemblyNote]  (no BOM)
ZZ7  Place Jumper SH-J6B on pins 5 and 6  [AssemblyNote]  (no BOM)
ZZ8  Place Jumper SH-J6C on pins 11 and 12  [AssemblyNote]  (no BOM)
ZZ9  Place Jumper SH-10 on pins 1 and 2  [AssemblyNote]  (no BOM)

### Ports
LED_0 (bidir), LED_GPIO (in)

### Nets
3V3: J6.6 J6.8
+1V8: C35.1 R14.2 U3.4(OUT)
AVD: D1.1(A) J6.10 J6.12
GND: C28.1 C29.2 C30.2 C31.2 C32.2 C33.2 C34.2 C35.2 C36.2 C37.2 C38.2 C39.2 D5.2(K) D7.2(K) GND1.1 R11.2 R12.1 R13.1 R15.1 R18.1 R21.1 R24.1 R27.1 T1.1 U3.3(GND) U3.6(TAB) U4.3(GND) U4.6(TAB) U5.3(GND) U5.6(TAB)
PWR_CHASSIS: C28.2 J5.6 J5.7 J5.8 J5.9 J5.10 J5.11 R11.1
VDDIO: D2.1(A) J6.2 J6.4 R16.1 R17.2 R22.1 R23.2
3V3_EXT: J6.7 J9.1
5V_20V: C29.1 C30.1 C31.1 C32.1 C33.1 C34.1 C36.1 C38.1 D3.1(K) U3.1(~{SHDN}) U3.2(IN) U4.1(~{SHDN}) U4.2(IN) U5.1(~{SHDN}) U5.2(IN) V+1.1
AVD_EXT: J6.9 J8.1
AVD_INT: C37.1 J6.5 J6.11 R19.2 U4.4(OUT)
LED_0: J10.2 ; port LED_0
LED_GPIO: J11.2 ; port LED_GPIO
VDDIO_EXT: J6.1 J7.1
VDDIO_INT: C39.1 J6.3 R26.2 U5.4(OUT)
NetD1_2: D1.2(K) R12.2
NetD2_2: D2.2(K) R13.2
NetD3_2: D3.2(A) T1.2
NetD4_1: D4.1(A) R17.1
NetD4_2: D4.2(K) J10.1 R16.2
NetD5_1: D5.1(A) R20.2
NetD6_1: D6.1(A) R23.1
NetD6_2: D6.2(K) J11.1 R22.2
NetD7_1: D7.1(A) R25.2
NetGND2_1: GND2.1 J5.5(GND) T1.4
NetJ5_1: J5.1(VBUS) T1.3 V+2.1
NetJ10_3: J10.3 R18.2 R20.1
NetJ11_3: J11.3 R24.2 R25.1
NetR14_1: R14.1 R15.2 U3.5(ADJ)
NetR19_1: R19.1 R21.2 U4.5(ADJ)
NetR26_1: R26.1 R27.2 U5.5(ADJ)

Not connected (* = marked no-connect by the designer): J5 2(D-)* 3(D+)* 4(ID)*

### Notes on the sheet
- Adjustable Supplies: (R19,R26)
  4.22K for 3.3V (default)
  2.56K for 2.5V
  1.2K for 1.8V

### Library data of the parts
C28 = 1812GC472KAT1A: as C51 on sheet SV601202B_AFE
C29 C37 C39 = CGA6P1X7R1C226M250AC: as C40 on sheet SV601202B_AFE
C30 C34 C36 C38 = CGA6P1X7R1E106M250AC: as C13 on sheet SV601202B_MAIN_BLOCK
C31 = CGA2B3X7R1H103K050BB: as C9 on sheet SV601202B_MAIN_BLOCK
C32 = CGA2B2C0G1H102J050BA: as C17 on sheet SV601202B_MAIN_BLOCK
C33 = CGA2B2C0G1H101J050BA: as C18 on sheet SV601202B_MAIN_BLOCK
C35 = CGA6P1X7R1E106M250AC: CAP, CERM, 10 µF, 25 V, +/- 20%, X7R, AEC-Q200 Grade 1, 1210; Manufacturer: TDK; Polarized: N; CompType: Capacitor; Value: 10uF; U/M: EA; Cap_F: 0.00001; Tolerance_%: 20; Value1: Unknown; VDC_V: 25; Value2: 25V; TaMin_C: -55; TaMax_C: 125; Cap_Case: 1210; SizeArea_mm2: 8; SizeAreaWB_mm2: 14.7; SizeX_mm: 3.2; SizeY_mm: 2.5; SizeZ_mm: 2.8; AEC Category: Q200; AEC Qualified: Y; AEC Grade: 1
D1 D2 D4-D7 = QTLP630C4TR: LED, Green, SMD; Manufacturer: Everlight; SymbolCreator: Altium; Vf_V: 2.1; Value2: 2.1V; Io_A: 0.02; Vr_V: 5; Tjmax_C: 85; Value1: W; Angle: 140; U/M: EA
D3 = NRVBA160T3G: Diode, Schottky, 60 V, 1 A, AEC-Q101, SMA; Manufacturer: ON Semiconductor; U/M: EA; Vf_V: 0.51; Value: 60V; Value1: 1A; Value2: 0.51V; Io_A: 1; Vr_V: 60; TJmax_C: 150; AEC Category: Q101; AEC Qualified: Y
GND1 GND2 J7-J9 V+1 V+2 = 1502-2: Terminal, Turret, TH, Double; Manufacturer: Keystone; CompType: Turret Terminal; U/M: EA
J5 = 0475890001: Connector, Receptacle, Micro-USB Type AB, R/A, Bottom Mount SMT; Manufacturer: Molex; SymbolCreator: a0411947
J6 = TSW-106-07-G-D: Header, 100mil, 6x2, Gold, TH; Manufacturer: Samtec; SymbolCreator: a0412235; U/M: EA
J10 J11 = TSW-103-07-G-S: Header, 100mil, 3x1, Gold, TH; Manufacturer: Samtec; SymbolCreator: a0799628; U/M: EA
R11 = CRCW12061M00FKEA: as R43 on sheet SV601202B_AFE
R12 R13 R17 R20 R23 R25 = CRCW0402470RJNED: RES, 470, 5%, 0.063 W, 0402; Manufacturer: Vishay-Dale; CompType: Resistor; Value: 470; Value_Code: 470R; Tolerance_%: 5; Power_W: 0.063; Value2: 0.063W; VDC_V: 50; TempCo: 200 ppm/C; EIA_Code: E24; U/M: EA
R14 = RT0603BRD071K2L: RES, 1.20 k, 0.1%, 0.1 W, 0603; Manufacturer: Yageo America; CompType: Resistor; Value: 1.20k; Res_ohm: 1200; Value_Code: 1k20; Tolerance_%: 0.1; Value2: 0.1W; VDC_V: 75; TempCo: 25 ppm/C; EIA_Code: E192; U/M: EA; AEC Category: Q200
R15 R21 R27 = ERA-3AEB242V: RES, 2.40 k, 0.1%, 0.1 W, AEC-Q200 Grade 0, 0603; Manufacturer: Panasonic; CompType: Resistor; Value: 2.40k; Res_ohm: 2400; Value_Code: 2k40; Tolerance_%: 0.1; Value2: 0.1W; VDC_V: 75; TempCo: 25 ppm/C; EIA_Code: E192; U/M: EA; AEC Category: Q200; AEC Qualified: Y; AEC Grade: 0
R16 R18 R22 R24 = CRCW04022K49FKED: RES, 2.49 k, 1%, 0.063 W, 0402; Manufacturer: Vishay-Dale; CompType: Resistor; Value: 2.49k; Res_ohm: 2490; Value_Code: 2k49; Tolerance_%: 1; Power_W: 0.063; Value2: 0.063W; VDC_V: 50; TempCo: 100 ppm/C; EIA_Code: E96; U/M: EA; AEC Category: Q200
R19 R26 = CRCW06034K22FKEA: RES, 4.22 k, 1%, 0.1 W, 0603; Manufacturer: Vishay-Dale; CompType: Resistor; Value: 4.22k; Res_ohm: 4220; Value_Code: 4k22; Tolerance_%: 1; Power_W: 0.1; Value2: 0.1W; VDC_V: 75; TempCo: 100 ppm/C; EIA_Code: E96; U/M: EA; AEC Category: Q200
SH-J6A SH-J6B SH-J6C SH-J10 = SPC02SYAN: as SH-J2 on sheet SV601202B_MAIN_BLOCK
T1 = ACM9070-701-2PL: Common Mode Filter for Power Line; Manufacturer: TDK; CompType: Transformer
U3-U5 = TL1963AQKTTRQ1: Single Output Fast Transient Response LDO, 1.5 A, Adjustable 1.21 to 20 V Output, 2.1 to 20 V Input, 5-pin DDPAK (KTT), -40 to 125 degC, Green (RoHS & no Sb/Br); Manufacturer: Texas Instruments; Alternate PartNumber: Equivalent; Iout(Max)(A): 1.5; Iq(Typ)(mA): 1; SubFamily: Single Channel LDO; Vdo(Typ)(mV): 340; Vin(Max)(V): 20; Vin(Min)(V): 2.1; Vout Adj(Min)(V): 1.21
ZZ6-ZZ9 = Assembly Note: SymbolCreator: codlsc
